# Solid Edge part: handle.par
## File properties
Title: Handle
Author: Robert a Rhodes jr
Template: Normal.par
Last saved by: Rajat Kamboj
Revision: 15
Application: Solid Edge
Accuracy: 0.99
Material: aluminum
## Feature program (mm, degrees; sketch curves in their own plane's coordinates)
sketch for "unnamed RevolvedProtrusion 1" plane through (0, 0, 0) normal (0, -1, 0) x-axis (1, 0, 0)
  line (-87.868, 0.2971) -> (-87.868, -4)
  line (-87.868, -4) -> (-79.868, -4)
  line (-79.868, -4) -> (-79.868, -5)
  line (-79.868, -5) -> (76.132, -5)
  line (76.132, -5) -> (76.132, -4)
  line (76.132, -4) -> (84.132, -4)
  line (84.132, -4) -> (84.132, 0.2971)
revolve "unnamed RevolvedProtrusion 1" add finite 360 deg about sketch line (-87.868, 0.2971) -> (84.132, 0.2971)
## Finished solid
Body 1: solid body, 7 faces, 6 edges, 0 vertices.
  Faces by surface: plane 4, cylinder 3
  Edges by curve: circle 6
Bounding box of the edges (mm): 172.000 x 10.594 x 10.594, from (-87.868, -5.2971, -5) to (84.132, 5.2971, 5.5941).
Cylindrical faces by radius (mm): R4.2971 x2, R5.2971 x1
Planar faces by outward normal: +x 2, -x 2
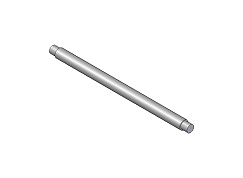
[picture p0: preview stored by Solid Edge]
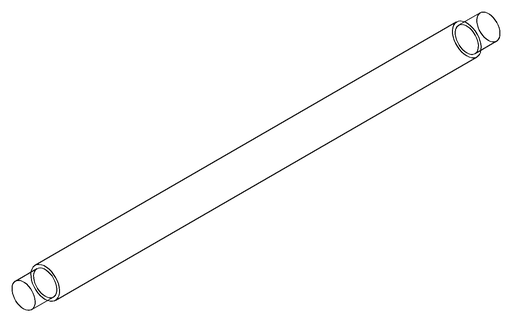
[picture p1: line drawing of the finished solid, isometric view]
